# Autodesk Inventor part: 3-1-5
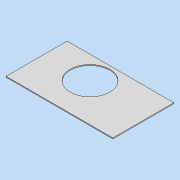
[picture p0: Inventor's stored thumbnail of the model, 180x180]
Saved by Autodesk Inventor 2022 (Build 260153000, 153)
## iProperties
Created: 2021-07
Part Number: 3-1-5
Material: 一般
Document SubType Name: Modeling
Designer: DesignLab
Density: 1 g/cm^3
Appearance: 既定
Author: DesignLab
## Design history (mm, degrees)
sketch "スケッチ1"
  geometry: L1 (0, 0)-(-350, 0); L2 (-350, 0)-(-350, -200); L3 (-350, -200)-(0, -200); L4 (0, -200)-(0, 0)
  constraints: 8 end point, 2 parallel, 1 horizontal, 1 perpendicular
  dimensions: "d0" = 350 distance of L3.end L2.end; "d1" = 200 distance of L2.end L1.end
extrude "押し出し1" new body sketch "スケッチ1" distance "d2" = 3; taper "d3" = 0 deg
sketch "スケッチ2"
  geometry: C1 r 65 at (150, 125); 1 further point
  constraints: 1 centre point
  dimensions: "d4" = 130 diameter of C1; "d5" = 150 horizontal distance of point (0, 0) C1.centre; "d6" = 125 vertical distance of C1.centre point (0, 0)
extrude "押し出し2" cut sketch "スケッチ2" distance "d7" = 3; taper "d8" = 0 deg
node "ソリッド1"
